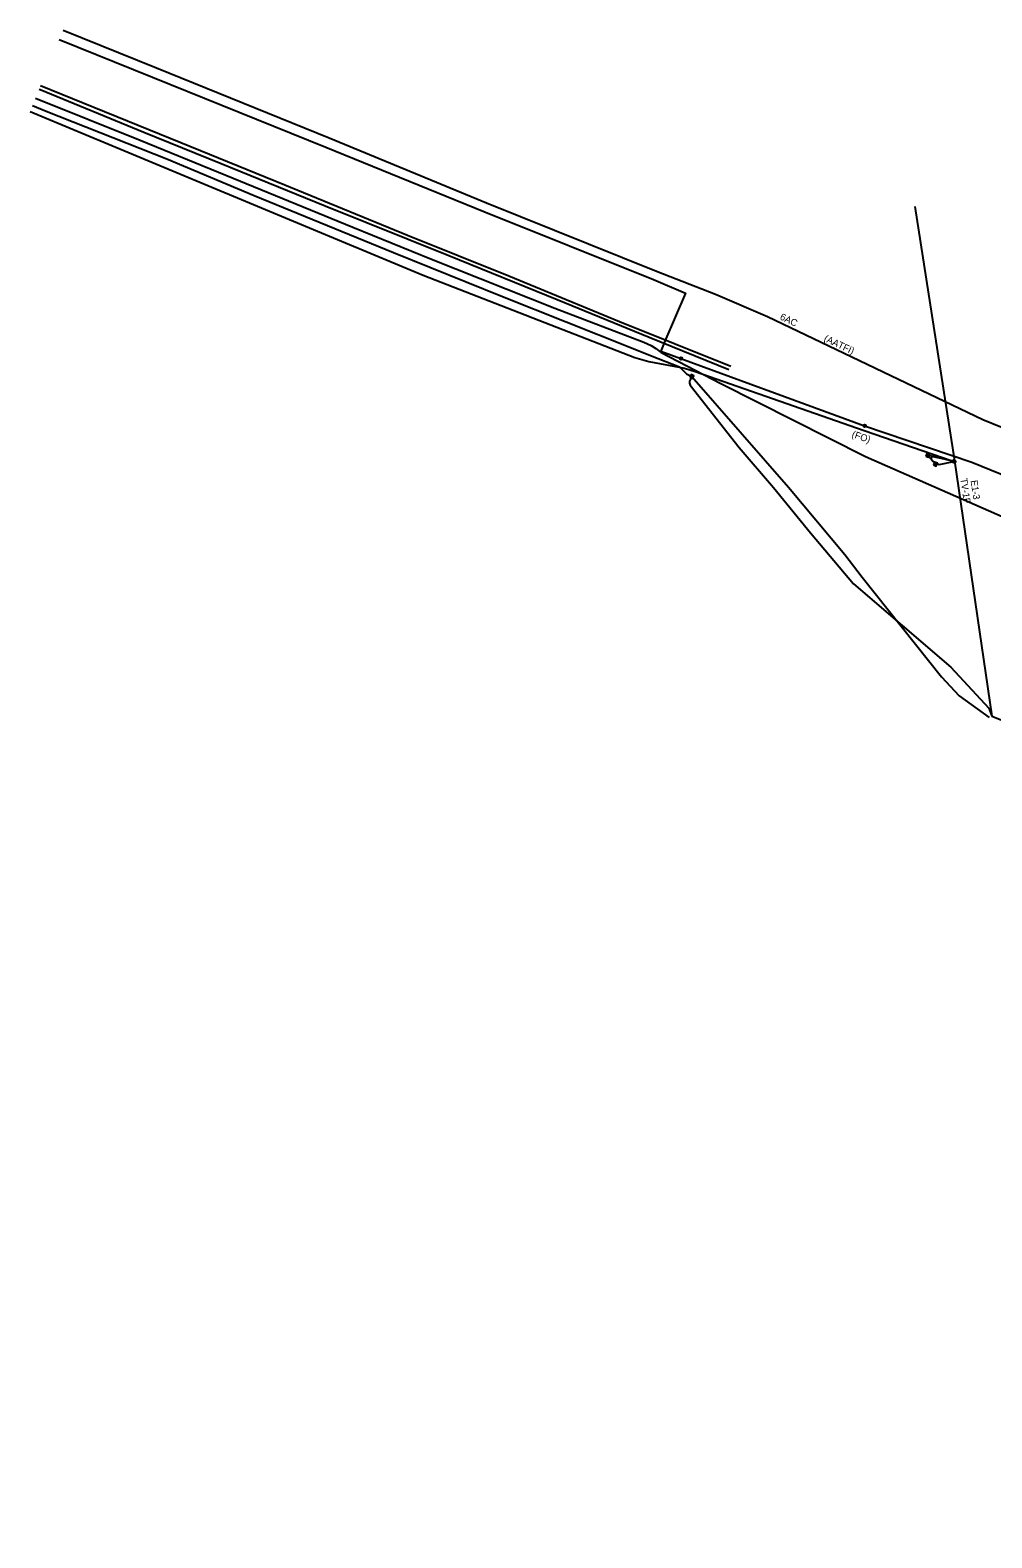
# Model space of a CAD drawing. Extents: x 2166631 to 2170707, y 207428 to 209111.
# Drawn here: x 2166631 to 2167156, y 208289 to 209111 of the extents above; entities that cross this region are included whole.
import ezdxf

# ---------------------------------------------------------------- set-up
doc = ezdxf.new("R2010")
doc.units = 0
for name, color, linetype in [('RD_EX_SU_H2O', 7, 'Continuous'), ('RD_EX_SU_Misc', 7, 'Continuous'), ('RD_EX_SU_Ovhd', 7, 'Continuous'), ('RD_EX_SU_Telecom', 7, 'Continuous'), ('RD_EX_SU_TX_H2O', 7, 'Continuous'), ('RD_EX_SU_TX_Ovhd', 7, 'Continuous'), ('RD_EX_SU_TX_Telecom', 7, 'Continuous')]:
    doc.layers.add(name, color=color, linetype=linetype)

msp = doc.modelspace()

# ---------------------------------------------------------------- linework, layer by layer
at = {"layer": 'RD_EX_SU_H2O'}
msp.add_line((2167086.45, 208895.51), (2167144.87, 208875.61), dxfattribs=at)
for points in [[(2166647.2, 209106.25), (2166697.98, 209085.72), (2166792.57, 209047.37), (2166878.81, 209012.33), (2166971.25, 208975.34), (2166988.79, 208967.79), (2166977.51, 208941.7)], [(2166649.23, 209111.27), (2166700.16, 209090.65), (2166794.32, 209052.46), (2166880.2, 209017.15), (2166972.94, 208979.79), (2167005.11, 208967.23)], [(2167005.11, 208967.23), (2167033.46, 208955.04), (2167150.83, 208898.91)], [(2166977.51, 208941.7), (2166975.28, 208936.14), (2167086.45, 208895.51)], [(2167150.83, 208898.91), (2167395.21, 208799.32), (2168738, 208252.12), (2168771.81, 208104.5), (2168930.48, 208039.81), (2169042.32, 208128.69), (2169791.43, 207823.92)], [(2167144.87, 208875.61), (2167820.52, 208600.61), (2168758.4, 208215.02), (2168781.36, 208111.79), (2168927.74, 208052.43), (2169006.44, 208114.13), (2169655.67, 207849.79), (2169781.62, 207799.98)]]:
    msp.add_lwpolyline(points, dxfattribs=at)
for centre in [(2166986.26, 208932.16), (2167086.45, 208895.51)]:
    msp.add_circle(centre, 0.719, dxfattribs=at)
at = {"layer": 'RD_EX_SU_Misc'}
msp.add_lwpolyline([(2166636.24, 209079.15), (2166636.72, 209078.95), (2166693.35, 209055.57), (2166735.51, 209038.47), (2166792.27, 209015.52), (2166859.65, 208988.39), (2166918.79, 208964.32), (2166968.83, 208943.81), (2167012.35, 208926.12)], dxfattribs=at)
at = {"layer": 'RD_EX_SU_Ovhd'}
for p, q in [((2167113.74, 209015.15), (2167135.55, 208876.33)), ((2167135.55, 208876.33), (2167155.83, 208737.15)), ((2167155.83, 208737.15), (2167653.47, 208539.12))]:
    msp.add_line(p, q, dxfattribs=at)
at = {"layer": 'RD_EX_SU_Telecom'}
for p, q in [((2167133.49, 208876.05), (2167134.24, 208876.05)), ((2167134.24, 208875.94), (2167135.14, 208876.84)), ((2167134.37, 208875.61), (2167135.47, 208876.72)), ((2167134.59, 208875.38), (2167135.7, 208876.49)), ((2167134.91, 208875.26), (2167135.83, 208876.17)), ((2167135.84, 208876.05), (2167136.58, 208876.05)), ((2167135.52, 208875.41), (2167135.67, 208875.56))]:
    msp.add_line(p, q, dxfattribs=at)
for points in [[(2166634.22, 209074.14), (2166691.37, 209051.28), (2166734.07, 209033.89), (2166807.2, 209003.73), (2166850.11, 208986.32), (2166917.45, 208959.73), (2166965.96, 208941.15)], [(2166637.02, 209081.07), (2166713.54, 209050.07), (2166770.28, 209026.92), (2166837.04, 208999.52), (2166892.36, 208977.23), (2166952.68, 208952.46), (2167013.45, 208928.09)], [(2166631.29, 209066.89), (2166845.74, 208977.55), (2166961.08, 208932.79), (2166968.78, 208930.5), (2166988.13, 208926.92), (2166994.04, 208925.13), (2167086.15, 208892.85), (2167134.24, 208876.44)], [(2166632.63, 209070.22), (2166640.1, 209067.11), (2166705.87, 209041), (2166753.51, 209021.01), (2166829.51, 208989.98), (2166888.9, 208966.07), (2166958.4, 208938.39), (2166969.66, 208933.9), (2166985.44, 208927.57), (2166989.37, 208923.75), (2166992.24, 208922.36), (2166990.89, 208919.82), (2166990.85, 208918.74), (2166991.35, 208917.57), (2167017.95, 208883.73), (2167036.66, 208861.85), (2167057, 208837.08), (2167080.3, 208809.31), (2167133.47, 208763.93), (2167154.22, 208741.56), (2167155.83, 208737.15)], [(2166965.96, 208941.15), (2166969.97, 208939.32), (2166972.54, 208937.72), (2166975.39, 208935.4), (2167008.01, 208918.47), (2167086.86, 208878.73), (2167173.38, 208840.74), (2167224.76, 208818.58), (2167737.21, 208591.61), (2169733.98, 207784.3), (2169769.15, 207779.36)], [(2166992.24, 208922.36), (2167044.84, 208861.93), (2167075.58, 208825.24)], [(2167135.04, 208876.05), (2167120.82, 208879.39), (2167125.07, 208874.6)], [(2167134.24, 208876.44), (2167123, 208878.69), (2167122.71, 208877.44), (2167123.64, 208876.2), (2167127.08, 208874.44), (2167135.14, 208875.99)], [(2167075.58, 208825.24), (2167085.17, 208812.9), (2167128.43, 208758.49), (2167138.04, 208748.28), (2167154.42, 208736.46)]]:
    msp.add_lwpolyline(points, dxfattribs=at)
for points in [[(2166991.19, 208921.92), (2166992.68, 208921.32), (2166993.28, 208922.81), (2166991.8, 208923.41)], [(2167119.77, 208878.95), (2167121.26, 208878.35), (2167121.87, 208879.83), (2167120.38, 208880.44)], [(2167124.02, 208874.16), (2167125.51, 208873.55), (2167126.12, 208875.04), (2167124.63, 208875.65)]]:
    msp.add_lwpolyline(points, close=True, dxfattribs=at)
msp.add_circle((2167135.04, 208876.05), 0.8, dxfattribs=at)

# ---------------------------------------------------------------- texts
at = {"layer": 'RD_EX_SU_H2O'}
for p in [(2166985.83, 208931.64), (2167086.02, 208894.99)]:
    msp.add_text('v', height=1.28, dxfattribs=at).set_placement(p)
at = {"layer": 'RD_EX_SU_Telecom'}
for s, height, rotation, p in [('t', 1.28, 337.89116, (2166991.78, 208921.89)), ('tv', 1.279, 337.80532, (2167120, 208879.09)), ('tv', 1.279, 337.80532, (2167124.24, 208874.29))]:
    msp.add_text(s, height=height, rotation=rotation, dxfattribs=at).set_placement(p)
at = {"layer": 'RD_EX_SU_TX_H2O'}
for s, p in [('6AC', (2167039.9, 208953.69)), ('(AATFI)', (2167063.87, 208941.9))]:
    msp.add_text(s, height=3.75, rotation=334.44121, dxfattribs=at).set_placement(p)
at = {"layer": 'RD_EX_SU_TX_Ovhd'}
for s, p in [('TV-1F', (2167138.63, 208866.63)), ('E1-3', (2167144.24, 208865.56))]:
    msp.add_text(s, height=3.75, rotation=278.29026, dxfattribs=at).set_placement(p)
at = {"layer": 'RD_EX_SU_TX_Telecom'}
msp.add_text('(FO)', height=3.75, rotation=340.68582, dxfattribs=at).set_placement((2167079.13, 208889.44))

doc.saveas('drawing.dxf')
